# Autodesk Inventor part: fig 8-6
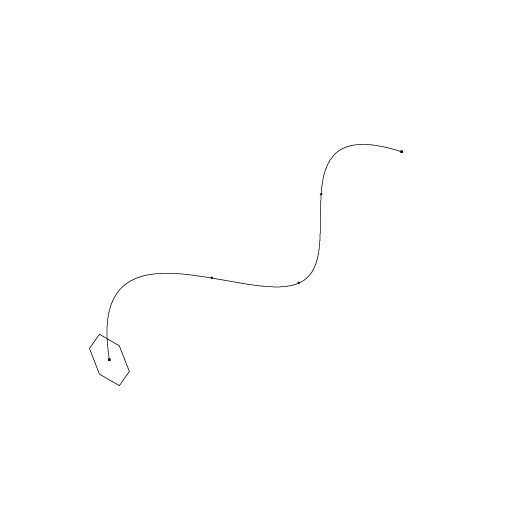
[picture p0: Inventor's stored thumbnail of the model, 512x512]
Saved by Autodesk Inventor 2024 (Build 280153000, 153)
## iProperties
Created: 2006-01
Part Number: fig 8-6
Document SubType Name: Modeling
Designer: CADCIM
Density: 1 g/cm^3
Material: Generic
Appearance: Default
Author: CADCIM
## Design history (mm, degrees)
sketch "Sketch1"
  geometry: 5 further points
  constraints: 5 other
sketch "Sketch2"
  geometry: L1 (-4.728, 0)-(-2.364, 4.094); L2 (-2.364, 4.094)-(2.364, 4.094); L3 (2.364, 4.094)-(4.728, 0); L4 (4.728, 0)-(2.364, -4.094); L5 (2.364, -4.094)-(-2.364, -4.094); L6 (-2.364, -4.094)-(-4.728, 0); 1 further point
  constraints: 12 end point, 13 other
body "Solid1"
